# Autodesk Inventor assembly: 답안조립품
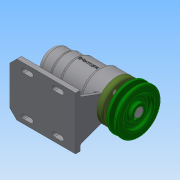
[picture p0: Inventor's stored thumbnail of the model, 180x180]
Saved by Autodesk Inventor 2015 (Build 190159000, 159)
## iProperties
Created: 2017-09
Part Number: 답안조립품
Document SubType Name: Assembly
Designer: owner
Author: owner
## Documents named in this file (12)
- C:\Users\owner\Desktop\470907V1002\답안조립품.iam
- C:\Users\owner\Desktop\470907V1002\본체.ipt
- C:\Users\owner\Desktop\470907V1002\베어링 51202.ipt
- C:\Users\owner\Desktop\470907V1002\어댑터슬리브.ipt
- C:\Users\owner\Desktop\470907V1002\베어링 6004.ipt
- C:\Users\owner\Desktop\470907V1002\축.ipt
- C:\Users\owner\Desktop\470907V1002\커버.ipt
- C:\Users\owner\Desktop\470907V1002\오일 실 20x35x7.ipt
- C:\Users\owner\Desktop\470907V1002\볼트 M4 x 12.ipt
- C:\Users\owner\Desktop\470907V1002\키 5 x 5 x 16.ipt
- C:\Users\owner\Desktop\470907V1002\V벨트풀리.ipt
- C:\Users\owner\Desktop\470907V1002\멈춤나사 M3x8.ipt
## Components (1 placed, 1 different names)
1. V벨트풀리:1 — 각도:1
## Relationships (1: Angle 1)
- 각도:1 [Angle]: V벨트풀리:1
